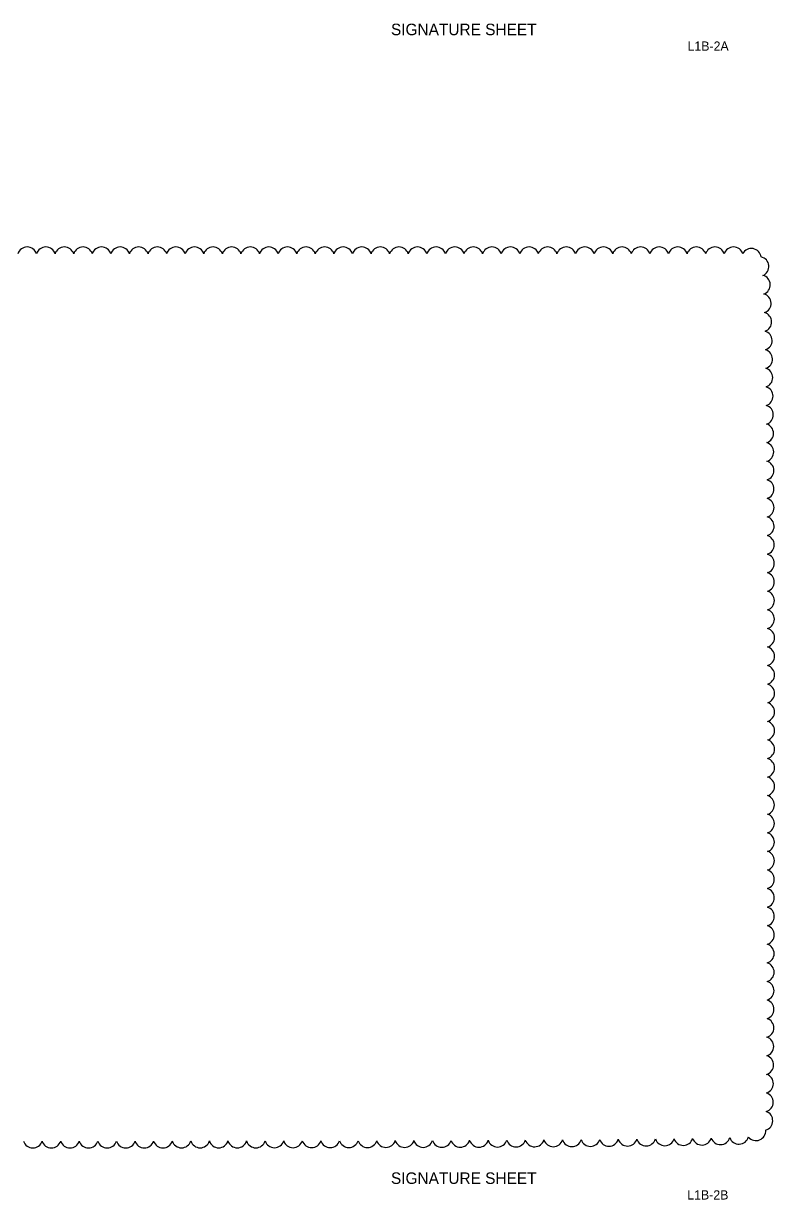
# Model space of a CAD drawing. Extents: x -811.2 to -795, y -2307.6 to -2235.1.
# Drawn here: x -803.18 to -795.04, y -2270.23 to -2257.47 of the extents above; entities that cross this region are included whole.
import ezdxf

# ---------------------------------------------------------------- set-up
doc = ezdxf.new("R2010")
doc.units = 0
for name, color, linetype in [('Cloud_dp', 7, 'Continuous'), ('Logo_dp', 7, 'Continuous'), ('NonPlottingEle_dp', 7, 'Continuous')]:
    doc.layers.add(name, color=color, linetype=linetype)

msp = doc.modelspace()

# ---------------------------------------------------------------- linework, layer by layer
at = {"layer": 'Cloud_dp'}
for centre, start, end in [((-803.143, -2260.002), 17.5, 162.5), ((-802.941, -2260.002), 17.5, 162.5), ((-802.74, -2260.002), 17.5, 162.5), ((-802.538, -2260.002), 17.5, 162.5), ((-802.337, -2260.002), 17.5, 162.5), ((-802.135, -2260.002), 17.5, 162.5), ((-801.934, -2260.002), 17.5, 162.5), ((-801.732, -2260.002), 17.5, 162.5), ((-801.531, -2260.002), 17.5, 162.5), ((-801.329, -2260.002), 17.5, 162.5), ((-801.128, -2260.002), 17.5, 162.5), ((-800.926, -2260.002), 17.5, 162.5), ((-800.724, -2260.002), 17.5, 162.5), ((-800.523, -2260.002), 17.5, 162.5), ((-800.321, -2260.002), 17.5, 162.5), ((-800.12, -2260.002), 17.5, 162.5), ((-799.918, -2260.002), 17.5, 162.5), ((-799.717, -2260.002), 17.5, 162.5), ((-799.515, -2260.002), 17.5, 162.5), ((-799.314, -2260.002), 17.5, 162.5), ((-799.112, -2260.002), 17.5, 162.5), ((-798.911, -2260.002), 17.5, 162.5), ((-798.709, -2260.002), 17.5, 162.5), ((-798.507, -2260.002), 17.5, 162.5), ((-798.306, -2260.002), 17.5, 162.5), ((-798.104, -2260.002), 17.5, 162.5), ((-797.903, -2260.002), 17.5, 162.5), ((-797.701, -2260.002), 17.5, 162.5), ((-797.5, -2260.002), 17.5, 162.5), ((-797.298, -2260.002), 17.5, 162.5), ((-797.097, -2260.002), 17.5, 162.5), ((-796.895, -2260.002), 17.5, 162.5), ((-796.693, -2260.002), 17.5, 162.5), ((-796.492, -2260.002), 17.5, 162.5), ((-796.29, -2260.002), 17.5, 162.5), ((-796.089, -2260.002), 17.5, 162.5), ((-795.887, -2260.002), 17.5, 162.5), ((-795.686, -2260.002), 17.5, 162.5), ((-795.484, -2260.002), 17.5, 162.5), ((-795.29, -2260.019), 7.7061, 152.7061), ((-795.207, -2260.108), 293.1451, 78.1451), ((-795.192, -2260.307), 290.3535, 75.3535), ((-795.183, -2260.508), 289.5186, 74.5186), ((-795.177, -2260.71), 289.0656, 74.0656), ((-795.172, -2260.911), 288.7699, 73.7699), ((-795.168, -2261.112), 288.5573, 73.5573), ((-795.165, -2261.314), 288.3949, 73.3949), ((-795.162, -2261.515), 288.2656, 73.2656), ((-795.159, -2261.717), 288.1595, 73.1595), ((-795.157, -2261.918), 288.0704, 73.0704), ((-795.155, -2262.12), 287.9942, 72.9942), ((-795.153, -2262.321), 287.928, 72.928), ((-795.152, -2262.523), 287.8698, 72.8698), ((-795.151, -2262.724), 287.8182, 72.8182), ((-795.15, -2262.926), 287.772, 72.772), ((-795.149, -2263.127), 287.7302, 72.7302), ((-795.148, -2263.329), 287.6923, 72.6923), ((-795.148, -2263.53), 287.6577, 72.6577), ((-795.147, -2263.732), 287.6259, 72.6259), ((-795.147, -2263.933), 287.5965, 72.5965), ((-795.146, -2264.135), 287.5693, 72.5693), ((-795.146, -2264.336), 287.544, 72.544), ((-795.146, -2264.538), 287.5204, 72.5204), ((-795.146, -2264.739), 287.5008, 72.5008), ((-795.146, -2264.941), 287.4924, 72.4924), ((-795.146, -2265.143), 287.4849, 72.4849), ((-795.146, -2265.344), 287.4769, 72.4769), ((-795.146, -2265.546), 287.4682, 72.4682), ((-795.146, -2265.747), 287.4589, 72.4589), ((-795.147, -2265.949), 287.4488, 72.4488), ((-795.147, -2266.15), 287.4378, 72.4378), ((-795.147, -2266.352), 287.4258, 72.4258), ((-795.147, -2266.553), 287.4126, 72.4126), ((-795.148, -2266.755), 287.398, 72.398), ((-795.148, -2266.956), 287.3817, 72.3817), ((-795.148, -2267.158), 287.3633, 72.3633), ((-795.149, -2267.359), 287.3425, 72.3425), ((-795.15, -2267.561), 287.3185, 72.3185), ((-795.15, -2267.763), 287.2905, 72.2905), ((-795.151, -2267.964), 287.2573, 72.2573), ((-795.152, -2268.166), 287.217, 72.217), ((-795.153, -2268.367), 287.1666, 72.1666), ((-795.154, -2268.569), 287.101, 72.101), ((-795.156, -2268.77), 287.0106, 72.0106), ((-795.158, -2268.972), 286.8744, 71.8744), ((-795.16, -2269.173), 286.6317, 71.6317), ((-795.165, -2269.374), 285.9387, 70.9387), ((-795.241, -2269.484), 219.2472, 4.2472), ((-803.082, -2269.563), 197.4989, 342.4989), ((-802.881, -2269.563), 197.5044, 342.5044), ((-802.679, -2269.563), 197.5105, 342.5105), ((-802.478, -2269.563), 197.5167, 342.5167), ((-802.276, -2269.563), 197.5233, 342.5233), ((-802.074, -2269.563), 197.5301, 342.5301), ((-801.873, -2269.563), 197.5372, 342.5372), ((-801.671, -2269.563), 197.5447, 342.5447), ((-801.47, -2269.562), 197.5525, 342.5525), ((-801.268, -2269.562), 197.5607, 342.5607), ((-801.067, -2269.562), 197.5693, 342.5693), ((-800.865, -2269.562), 197.5784, 342.5784), ((-800.664, -2269.562), 197.5879, 342.5879), ((-800.462, -2269.561), 197.598, 342.598), ((-800.261, -2269.561), 197.6087, 342.6087), ((-800.059, -2269.56), 197.62, 342.62), ((-799.858, -2269.56), 197.6321, 342.6321), ((-799.656, -2269.559), 197.6449, 342.6449), ((-799.454, -2269.559), 197.6587, 342.6587), ((-799.253, -2269.558), 197.6734, 342.6734), ((-799.051, -2269.558), 197.6893, 342.6893), ((-798.85, -2269.557), 197.7064, 342.7064), ((-798.648, -2269.556), 197.725, 342.725), ((-798.447, -2269.555), 197.7453, 342.7453), ((-798.245, -2269.555), 197.7675, 342.7675), ((-798.044, -2269.554), 197.792, 342.792), ((-797.842, -2269.552), 197.8192, 342.8192), ((-797.641, -2269.551), 197.8496, 342.8496), ((-797.439, -2269.55), 197.8839, 342.8839), ((-797.238, -2269.549), 197.9231, 342.9231), ((-797.036, -2269.547), 197.9684, 342.9684), ((-796.835, -2269.545), 198.0216, 343.0216), ((-796.633, -2269.543), 198.0853, 343.0853), ((-796.432, -2269.541), 198.1633, 343.1633), ((-796.23, -2269.539), 198.2623, 343.2623), ((-796.029, -2269.536), 198.3936, 343.3936), ((-795.827, -2269.532), 198.5799, 343.5799), ((-795.626, -2269.528), 198.8753, 343.8753), ((-795.425, -2269.522), 199.4643, 344.4643)]:
    msp.add_arc(centre, 0.106, start, end, dxfattribs=at)

# ---------------------------------------------------------------- texts
at = {"layer": 'Logo_dp'}
for p in [(-799.524, -2257.599), (-799.524, -2270.06)]:
    msp.add_text('       SIGNATURE SHEET         ', height=0.125, dxfattribs=at).set_placement(p)
at = {"layer": 'NonPlottingEle_dp'}
for s, p in [('L1B-2A ', (-795.983, -2257.767)), ('L1B-2B ', (-795.986, -2270.229))]:
    msp.add_text(s, height=0.1, dxfattribs=at).set_placement(p)

doc.saveas('drawing.dxf')
